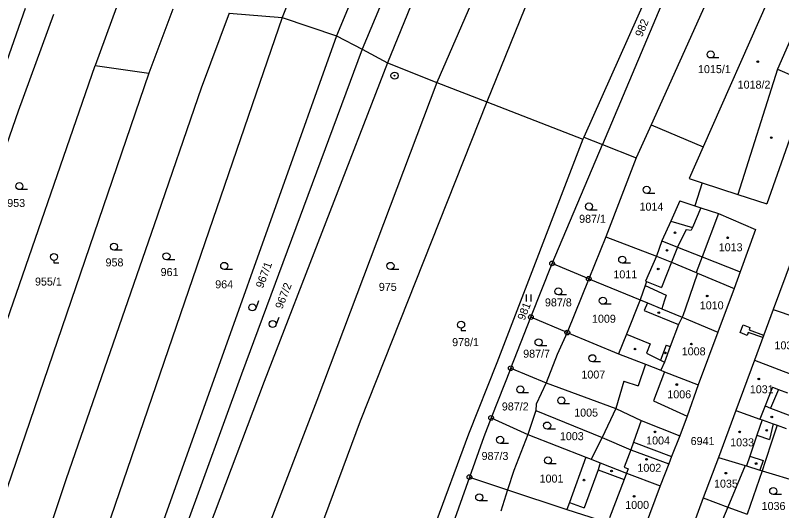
# Model space of a CAD drawing. Extents: x -593183 to -588034, y -1130415 to -1124994.
# Drawn here: x -591341.4 to -591178.8, y -1129005.4 to -1128900.2 of the extents above; entities that cross this region are included whole.
import ezdxf

# ---------------------------------------------------------------- set-up
doc = ezdxf.new("R2010")
doc.units = 0
for name, color, linetype in [('Vrstva 1', 7, 'Continuous'), ('Vrstva 18', 7, 'Continuous'), ('Vrstva 19', 7, 'Continuous'), ('Vrstva 24', 7, 'Continuous'), ('Vrstva 25', 7, 'Continuous'), ('Vrstva 27', 7, 'Continuous'), ('Vrstva 4', 7, 'Continuous')]:
    doc.layers.add(name, color=color, linetype=linetype)

msp = doc.modelspace()

# ---------------------------------------------------------------- linework, layer by layer
at = {"layer": 'Vrstva 1'}
for p, q in [((-591253.18, -1128872.07), (-591267.84, -1128907.4)), ((-591274.92, -1128875.91), (-591284.82, -1128900.6)), ((-591247.97, -1128874.78), (-591262.45, -1128910.29)), ((-591184.96, -1128875.53), (-591206.44, -1128923.42)), ((-591195.75, -1128877.7), (-591216.83, -1128927.62)), ((-591263.41, -1128880.52), (-591273.24, -1128904.52)), ((-591200.68, -1128880.96), (-591220.77, -1128926.07)), ((-591240.16, -1128887.18), (-591251.97, -1128914.47)), ((-591228.37, -1128886.57), (-591241.39, -1128918.58)), ((-591339.33, -1128898.75), (-591375.16, -1128999.99)), ((-591319.94, -1128898.41), (-591324.51, -1128910.84)), ((-591181.77, -1128897.25), (-591195.46, -1128928.12)), ((-591333.32, -1128900.02), (-591340.85, -1128920.55)), ((-591308.02, -1128898.88), (-591313.09, -1128912.48)), ((-591296.04, -1128899.72), (-591301.97, -1128915.65)), ((-591284.82, -1128900.6), (-591291.2, -1128919.2)), ((-591284.82, -1128900.6), (-591273.24, -1128904.52)), ((-591273.24, -1128904.52), (-591298.3, -1128974.83)), ((-591273.24, -1128904.52), (-591267.84, -1128907.4)), ((-591267.84, -1128907.4), (-591293.42, -1128976.43)), ((-591267.84, -1128907.4), (-591262.45, -1128910.29)), ((-591355.26, -1128999.87), (-591324.51, -1128910.84)), ((-591262.45, -1128910.29), (-591288.59, -1128978.01)), ((-591313.09, -1128912.48), (-591344.14, -1129003.51)), ((-591251.97, -1128914.47), (-591277.46, -1128982.03)), ((-591172.91, -1128914.55), (-591181.94, -1128940.23)), ((-591301.97, -1128915.65), (-591311.94, -1128944.66)), ((-591291.2, -1128919.2), (-591301.21, -1128948.55)), ((-591241.39, -1128918.58), (-591268.23, -1128986.43)), ((-591340.85, -1128920.55), (-591369.1, -1129001.43)), ((-591206.44, -1128923.42), (-591209.64, -1128930.47)), ((-591206.44, -1128923.42), (-591195.46, -1128928.12)), ((-591220.77, -1128926.07), (-591220.95, -1128926.48)), ((-591220.77, -1128926.07), (-591216.83, -1128927.62)), ((-591220.95, -1128926.48), (-591239.26, -1128974.04)), ((-591227.51, -1128952.91), (-591216.83, -1128927.62)), ((-591216.83, -1128927.62), (-591209.64, -1128930.47)), ((-591195.46, -1128928.12), (-591198.43, -1128934.82)), ((-591209.64, -1128930.47), (-591216.07, -1128947.22)), ((-591198.43, -1128934.82), (-591195.67, -1128935.75)), ((-591195.67, -1128935.75), (-591197.19, -1128940.68)), ((-591195.67, -1128935.75), (-591188.07, -1128938.22)), ((-591188.07, -1128938.22), (-591181.94, -1128940.23)), ((-591200.37, -1128939.61), (-591202.32, -1128943.95)), ((-591200.37, -1128939.61), (-591197.19, -1128940.68)), ((-591197.19, -1128940.68), (-591195.93, -1128941.07)), ((-591195.93, -1128941.07), (-591192.15, -1128942.26)), ((-591192.15, -1128942.26), (-591184.3, -1128945.67)), ((-591202.32, -1128943.95), (-591204.18, -1128948.09)), ((-591311.94, -1128944.66), (-591330.63, -1128998.65)), ((-591184.3, -1128945.67), (-591187.56, -1128954.71)), ((-591216.07, -1128947.22), (-591219.73, -1128956.16)), ((-591216.07, -1128947.22), (-591205.37, -1128951.32)), ((-591301.21, -1128948.55), (-591334.86, -1129046.79)), ((-591204.18, -1128948.09), (-591205.37, -1128951.32)), ((-591205.37, -1128951.32), (-591207.68, -1128956.69)), ((-591205.37, -1128951.32), (-591202.16, -1128952.64)), ((-591176.52, -1128951.85), (-591180.58, -1128962.67)), ((-591232, -1128964.3), (-591227.51, -1128952.91)), ((-591219.73, -1128956.16), (-591227.51, -1128952.91)), ((-591202.16, -1128952.64), (-591196.89, -1128954.81)), ((-591196.89, -1128954.81), (-591196.64, -1128954.95)), ((-591196.64, -1128954.95), (-591188.82, -1128958.23)), ((-591187.56, -1128954.71), (-591188.82, -1128958.23)), ((-591219.73, -1128956.16), (-591224.27, -1128967.58)), ((-591219.73, -1128956.16), (-591208.84, -1128960.65)), ((-591207.47, -1128956.77), (-591207.76, -1128957.61)), ((-591207.68, -1128956.69), (-591207.47, -1128956.77)), ((-591207.76, -1128957.61), (-591208.84, -1128960.65)), ((-591188.82, -1128958.23), (-591192.3, -1128967.48)), ((-591208.84, -1128960.65), (-591211.74, -1128967.96)), ((-591208.84, -1128960.65), (-591207.28, -1128961.3)), ((-591207.28, -1128961.3), (-591204.23, -1128962.53)), ((-591204.23, -1128962.53), (-591199.88, -1128964.31)), ((-591180.58, -1128962.67), (-591184.55, -1128973.43)), ((-591180.58, -1128962.67), (-591175.73, -1128964.35)), ((-591236.29, -1128975.17), (-591232, -1128964.3)), ((-591224.27, -1128967.58), (-591232, -1128964.3)), ((-591199.88, -1128964.31), (-591192.3, -1128967.48)), ((-591224.27, -1128967.58), (-591226.42, -1128972.22)), ((-591224.27, -1128967.58), (-591213.4, -1128972.12)), ((-591211.74, -1128967.96), (-591213.4, -1128972.12)), ((-591192.3, -1128967.48), (-591196.48, -1128978.68)), ((-591226.42, -1128972.22), (-591228.79, -1128978.29)), ((-591213.4, -1128972.12), (-591207.67, -1128974.33)), ((-591184.55, -1128973.43), (-591188.48, -1128984.14)), ((-591184.55, -1128973.43), (-591176.03, -1128976.71)), ((-591298.3, -1128974.83), (-591327.17, -1129055.6)), ((-591239.26, -1128974.04), (-591245.26, -1128989.18)), ((-591236.29, -1128975.17), (-591240.44, -1128985.71)), ((-591236.29, -1128975.17), (-591228.79, -1128978.29)), ((-591207.67, -1128974.33), (-591209.24, -1128978.92)), ((-591207.67, -1128974.33), (-591204.4, -1128975.59)), ((-591293.42, -1128976.43), (-591322.65, -1129056.55)), ((-591204.4, -1128975.59), (-591203.61, -1128975.94)), ((-591203.61, -1128975.94), (-591196.48, -1128978.68)), ((-591288.59, -1128978.01), (-591317.17, -1129053.44)), ((-591228.79, -1128978.29), (-591230.87, -1128982.83)), ((-591228.79, -1128978.29), (-591213.98, -1128983.73)), ((-591212.29, -1128977.95), (-591213.98, -1128983.73)), ((-591212.29, -1128977.95), (-591209.24, -1128978.92)), ((-591196.48, -1128978.68), (-591198.85, -1128985.35)), ((-591277.46, -1128982.03), (-591307.81, -1129061.25)), ((-591230.87, -1128982.83), (-591230.99, -1128984.17)), ((-591230.99, -1128984.17), (-591232.62, -1128989.23)), ((-591230.99, -1128984.17), (-591216.89, -1128989.86)), ((-591213.98, -1128983.73), (-591216.89, -1128989.86)), ((-591213.98, -1128983.73), (-591208.57, -1128986.31)), ((-591188.48, -1128984.14), (-591192.18, -1128994.11)), ((-591188.48, -1128984.14), (-591183.39, -1128985.97)), ((-591268.23, -1128986.43), (-591298.24, -1129066.98)), ((-591240.44, -1128985.71), (-591242.02, -1128989.72)), ((-591240.44, -1128985.71), (-591232.62, -1128989.23)), ((-591208.57, -1128986.31), (-591200.42, -1128989.51)), ((-591198.85, -1128985.35), (-591200.42, -1128989.51)), ((-591183.39, -1128985.97), (-591182.92, -1128986.14)), ((-591182.92, -1128986.14), (-591180.57, -1128986.99)), ((-591179.75, -1128987.29), (-591180.79, -1128990.47)), ((-591180.57, -1128986.99), (-591179.75, -1128987.29)), ((-591179.75, -1128987.29), (-591177.84, -1128987.98)), ((-591245.26, -1128989.18), (-591262.07, -1129034.56)), ((-591242.02, -1128989.72), (-591245.06, -1128998.31)), ((-591232.62, -1128989.23), (-591235.61, -1128996.93)), ((-591232.62, -1128989.23), (-591220.36, -1128994.07)), ((-591216.89, -1128989.86), (-591219.21, -1128994.52)), ((-591216.89, -1128989.86), (-591210.78, -1128992.5)), ((-591200.42, -1128989.51), (-591202.14, -1128993.93)), ((-591180.79, -1128990.47), (-591182.26, -1128994.96)), ((-591210.78, -1128992.5), (-591202.75, -1128995.52)), ((-591220.36, -1128994.07), (-591223.82, -1129003.72)), ((-591220.36, -1128994.07), (-591219.21, -1128994.52)), ((-591219.21, -1128994.52), (-591217.27, -1128995.28)), ((-591202.14, -1128993.93), (-591202.75, -1128995.52)), ((-591192.18, -1128994.11), (-591195.42, -1129002.71)), ((-591192.18, -1128994.11), (-591186.53, -1128995.85)), ((-591217.27, -1128995.28), (-591211.71, -1128997.45)), ((-591202.75, -1128995.52), (-591204.58, -1129000.17)), ((-591186.53, -1128995.85), (-591186.22, -1128995.94)), ((-591186.22, -1128995.94), (-591183.38, -1128996.82)), ((-591182.26, -1128994.96), (-591182.91, -1128996.96)), ((-591235.61, -1128996.93), (-591236.94, -1129001.02)), ((-591211.71, -1128997.45), (-591204.58, -1129000.17)), ((-591182.91, -1128996.96), (-591186.06, -1129006.21)), ((-591183.38, -1128996.82), (-591182.91, -1128996.96)), ((-591182.91, -1128996.96), (-591174.67, -1128999.49)), ((-591330.63, -1128998.65), (-591343.79, -1129037.78)), ((-591245.06, -1128998.31), (-591249.19, -1129010.01)), ((-591245.06, -1128998.31), (-591236.94, -1129001.02)), ((-591236.94, -1129001.02), (-591238.41, -1129005.57)), ((-591236.94, -1129001.02), (-591224.34, -1129005.16)), ((-591204.58, -1129000.17), (-591208.07, -1129009.58)), ((-591195.42, -1129002.71), (-591199.39, -1129013.48)), ((-591195.42, -1129002.71), (-591190.18, -1129004.67)), ((-591223.82, -1129003.72), (-591224.34, -1129005.16)), ((-591224.34, -1129005.16), (-591217.72, -1129007.34)), ((-591190.18, -1129004.67), (-591186.06, -1129006.21))]:
    msp.add_line(p, q, dxfattribs=at)
at = {"layer": 'Vrstva 24'}
for centre, radius in [((-591260.95, -1128912.99), 0.75), ((-591260.95, -1128912.99), 0.0903), ((-591227.51, -1128952.91), 0.5), ((-591227.51, -1128952.91), 0.0327), ((-591219.73, -1128956.16), 0.5), ((-591219.73, -1128956.16), 0.0327), ((-591232, -1128964.3), 0.5), ((-591232, -1128964.3), 0.0327), ((-591224.27, -1128967.58), 0.5), ((-591224.27, -1128967.58), 0.0327), ((-591236.29, -1128975.17), 0.5), ((-591236.29, -1128975.17), 0.0327), ((-591240.44, -1128985.71), 0.5), ((-591240.44, -1128985.71), 0.0327), ((-591245.06, -1128998.31), 0.5), ((-591245.06, -1128998.31), 0.0327)]:
    msp.add_circle(centre, radius, dxfattribs=at)
at = {"layer": 'Vrstva 25'}
for p, q in [((-591192.09, -1128909.24), (-591193.84, -1128909.24)), ((-591338.83, -1128937.22), (-591340.58, -1128937.22)), ((-591205.67, -1128938.01), (-591207.42, -1128938.01)), ((-591217.92, -1128941.55), (-591219.67, -1128941.55)), ((-591318.76, -1128950.08), (-591320.51, -1128950.08)), ((-591333.25, -1128952.27), (-591333.25, -1128952.77)), ((-591307.61, -1128952.13), (-591309.36, -1128952.13)), ((-591333.25, -1128952.77), (-591332.23, -1128952.77)), ((-591210.86, -1128952.86), (-591212.61, -1128952.86)), ((-591295.35, -1128954.17), (-591297.1, -1128954.17)), ((-591260.06, -1128954.17), (-591261.81, -1128954.17)), ((-591232.98, -1128959.5), (-591232.98, -1128961)), ((-591231.96, -1128961), (-591231.96, -1128959.5)), ((-591224.44, -1128959.59), (-591226.19, -1128959.59)), ((-591289.86, -1128960.82), (-591290.41, -1128962.48)), ((-591214.98, -1128961.58), (-591216.73, -1128961.58)), ((-591285.49, -1128964.41), (-591286.13, -1128966.04)), ((-591246.82, -1128966.67), (-591246.82, -1128967.17)), ((-591246.82, -1128967.17), (-591245.8, -1128967.17)), ((-591228.63, -1128970.42), (-591230.38, -1128970.42)), ((-591217.2, -1128973.79), (-591218.95, -1128973.79)), ((-591232.5, -1128980.43), (-591234.25, -1128980.43)), ((-591223.8, -1128982.76), (-591225.55, -1128982.76)), ((-591226.8, -1128988.1), (-591228.55, -1128988.1)), ((-591236.79, -1128991.14), (-591238.54, -1128991.14)), ((-591226.63, -1128995.5), (-591228.38, -1128995.5)), ((-591178.81, -1129002.02), (-591180.56, -1129002.02)), ((-591241.22, -1129003.36), (-591242.97, -1129003.36))]:
    msp.add_line(p, q, dxfattribs=at)
for centre, radius in [((-591193.84, -1128908.49), 0.75), ((-591183.84, -1128910.03), 0.175), ((-591183.84, -1128910.03), 0.15), ((-591180.97, -1128926.16), 0.175), ((-591340.58, -1128936.47), 0.75), ((-591207.42, -1128937.26), 0.75), ((-591219.67, -1128940.8), 0.75), ((-591201.4, -1128946.38), 0.175), ((-591190.25, -1128947.45), 0.175), ((-591190.25, -1128947.45), 0.15), ((-591320.51, -1128949.33), 0.75), ((-591333.25, -1128951.52), 0.75), ((-591309.36, -1128951.38), 0.75), ((-591203.11, -1128950.13), 0.175), ((-591212.61, -1128952.11), 0.75), ((-591297.1, -1128953.42), 0.75), ((-591261.81, -1128953.42), 0.75), ((-591204.97, -1128954.08), 0.175), ((-591226.19, -1128958.84), 0.75), ((-591216.73, -1128960.83), 0.75), ((-591194.57, -1128959.81), 0.175), ((-591194.57, -1128959.81), 0.15), ((-591291.12, -1128962.24), 0.75), ((-591204.85, -1128963.36), 0.175), ((-591286.83, -1128965.77), 0.75), ((-591246.82, -1128965.92), 0.75), ((-591230.38, -1128969.67), 0.75), ((-591197.93, -1128970.03), 0.175), ((-591197.93, -1128970.03), 0.15), ((-591209.89, -1128971.09), 0.175), ((-591203.48, -1128971.9), 0.175), ((-591218.95, -1128973.04), 0.75), ((-591201.04, -1128978.63), 0.175), ((-591201.04, -1128978.63), 0.15), ((-591183.62, -1128977.45), 0.175), ((-591183.62, -1128977.45), 0.15), ((-591234.25, -1128979.68), 0.75), ((-591225.55, -1128982.01), 0.75), ((-591228.55, -1128987.35), 0.75), ((-591180.87, -1128985.52), 0.175), ((-591181.94, -1128988.36), 0.175), ((-591238.54, -1128990.39), 0.75), ((-591205.65, -1128988.69), 0.175), ((-591205.65, -1128988.69), 0.15), ((-591187.68, -1128988.69), 0.175), ((-591187.68, -1128988.69), 0.15), ((-591228.38, -1128994.75), 0.75), ((-591207.45, -1128994.52), 0.175), ((-591207.45, -1128994.52), 0.15), ((-591184.19, -1128995.43), 0.175), ((-591214.89, -1128997.01), 0.175), ((-591190.61, -1128997.47), 0.175), ((-591190.61, -1128997.47), 0.15), ((-591220.73, -1128998.94), 0.175), ((-591180.56, -1129001.27), 0.75), ((-591242.97, -1129002.61), 0.75), ((-591210.09, -1129002.4), 0.175), ((-591210.09, -1129002.4), 0.15)]:
    msp.add_circle(centre, radius, dxfattribs=at)
at = {"layer": 'Vrstva 27'}
for p, q in [((-591187.56, -1128967.58), (-591186.97, -1128965.98)), ((-591186.97, -1128965.98), (-591185.5, -1128966.54)), ((-591185.5, -1128966.54), (-591185.66, -1128967)), ((-591185.66, -1128967), (-591182.6, -1128968.14)), ((-591186.07, -1128968.18), (-591187.56, -1128967.58)), ((-591185.88, -1128967.58), (-591186.07, -1128968.18)), ((-591182.79, -1128968.67), (-591185.88, -1128967.58)), ((-591182.6, -1128968.14), (-591182.79, -1128968.67))]:
    msp.add_line(p, q, dxfattribs=at)
at = {"layer": 'Vrstva 4'}
for p, q in [((-591296.04, -1128899.72), (-591284.82, -1128900.6)), ((-591174.74, -1128900.32), (-591179.64, -1128911.6)), ((-591324.51, -1128910.84), (-591313.09, -1128912.48)), ((-591262.45, -1128910.29), (-591251.97, -1128914.47)), ((-591179.64, -1128911.6), (-591188.07, -1128938.22)), ((-591179.64, -1128911.6), (-591176.05, -1128913.15)), ((-591251.97, -1128914.47), (-591241.39, -1128918.58)), ((-591241.39, -1128918.58), (-591220.95, -1128926.48)), ((-591195.93, -1128941.07), (-591197.71, -1128945.29)), ((-591192.15, -1128942.26), (-591195.67, -1128951.5)), ((-591202.32, -1128943.95), (-591197.71, -1128945.29)), ((-591199.02, -1128945.7), (-591200.89, -1128949.44)), ((-591199.02, -1128945.7), (-591197.95, -1128945.86)), ((-591197.71, -1128945.29), (-591197.95, -1128945.86)), ((-591204.18, -1128948.09), (-591200.89, -1128949.44)), ((-591200.89, -1128949.44), (-591202.16, -1128952.64)), ((-591200.89, -1128949.44), (-591195.67, -1128951.5)), ((-591195.67, -1128951.5), (-591196.89, -1128954.81)), ((-591195.67, -1128951.5), (-591187.56, -1128954.71)), ((-591202.16, -1128952.64), (-591204.31, -1128958.03)), ((-591196.64, -1128954.95), (-591199.21, -1128962.38)), ((-591207.47, -1128956.77), (-591204.31, -1128958.03)), ((-591207.76, -1128957.61), (-591203.3, -1128959.61)), ((-591203.3, -1128959.61), (-591203.67, -1128960.73)), ((-591207.28, -1128961.3), (-591207.93, -1128962.88)), ((-591204.02, -1128961.86), (-591204.23, -1128962.53)), ((-591203.67, -1128960.73), (-591204.02, -1128961.86)), ((-591207.93, -1128962.88), (-591200.67, -1128965.88)), ((-591199.21, -1128962.38), (-591199.78, -1128964.02)), ((-591199.88, -1128964.31), (-591200.67, -1128965.88)), ((-591199.78, -1128964.02), (-591199.88, -1128964.31)), ((-591200.67, -1128965.88), (-591202.46, -1128970.55)), ((-591211.74, -1128967.96), (-591206.7, -1128969.96)), ((-591206.7, -1128969.96), (-591207.49, -1128971.95)), ((-591203.26, -1128970.24), (-591204.51, -1128973.44)), ((-591203.26, -1128970.24), (-591202.46, -1128970.55)), ((-591207.49, -1128971.95), (-591204.51, -1128973.44)), ((-591202.46, -1128970.55), (-591203.62, -1128973.88)), ((-591204.51, -1128973.44), (-591203.62, -1128973.88)), ((-591203.62, -1128973.88), (-591204.4, -1128975.59)), ((-591203.61, -1128975.94), (-591205.96, -1128982.07)), ((-591180.74, -1128979.17), (-591182.3, -1128983.17)), ((-591179.43, -1128979.67), (-591181.13, -1128983.63)), ((-591180.74, -1128979.17), (-591179.43, -1128979.67)), ((-591179.43, -1128979.67), (-591177.52, -1128980.42)), ((-591205.96, -1128982.07), (-591198.85, -1128985.35)), ((-591182.3, -1128983.17), (-591183.39, -1128985.97)), ((-591182.3, -1128983.17), (-591181.13, -1128983.63)), ((-591181.13, -1128983.63), (-591176.8, -1128985.31)), ((-591208.57, -1128986.31), (-591210.21, -1128990.9)), ((-591182.92, -1128986.14), (-591184.02, -1128989.4)), ((-591180.57, -1128986.99), (-591181.32, -1128990.31)), ((-591184.02, -1128989.4), (-591185.53, -1128993.89)), ((-591184.02, -1128989.4), (-591181.32, -1128990.31)), ((-591210.21, -1128990.9), (-591210.78, -1128992.5)), ((-591210.21, -1128990.9), (-591202.14, -1128993.93)), ((-591210.78, -1128992.5), (-591212.21, -1128996.22)), ((-591185.53, -1128993.89), (-591186.22, -1128995.94)), ((-591185.53, -1128993.89), (-591182.72, -1128994.81)), ((-591217.27, -1128995.28), (-591217.73, -1128996.77)), ((-591212.21, -1128996.22), (-591211.37, -1128996.52)), ((-591186.53, -1128995.85), (-591190.18, -1129004.67)), ((-591182.72, -1128994.81), (-591183.38, -1128996.82)), ((-591217.73, -1128996.77), (-591220.7, -1129004.84)), ((-591217.73, -1128996.77), (-591212.2, -1128998.8)), ((-591211.71, -1128997.45), (-591212.2, -1128998.8)), ((-591211.37, -1128996.52), (-591211.71, -1128997.45)), ((-591212.2, -1128998.8), (-591215.33, -1129006.95)), ((-591223.82, -1129003.72), (-591220.7, -1129004.84)), ((-591190.18, -1129004.67), (-591191.3, -1129007.38))]:
    msp.add_line(p, q, dxfattribs=at)

# ---------------------------------------------------------------- texts
at = {"layer": 'Vrstva 18'}
for s, rotation, p in [('982', 67.3996, (-591208.41, -1128904.91)), ('967/1', 69.6671, (-591288.88, -1128958.29)), ('967/2', 68.8934, (-591284.78, -1128962.72)), ('981', 68.499, (-591233.37, -1128965.13))]:
    msp.add_text(s, height=1.7, rotation=rotation, dxfattribs=at).set_placement(p)
for s, p in [('1015/1', (-591196.53, -1128912.46)), ('953', (-591343.16, -1128940.9)), ('1014', (-591208.94, -1128941.68)), ('987/1', (-591221.76, -1128944.26)), ('958', (-591322.29, -1128953.53)), ('961', (-591310.6, -1128955.58)), ('1011', (-591214.49, -1128956.07)), ('955/1', (-591337.27, -1128957.6)), ('964', (-591299.01, -1128958.18)), ('975', (-591264.28, -1128958.73)), ('987/8', (-591229.02, -1128962.03)), ('1009', (-591219.03, -1128965.5)), ('978/1', (-591248.72, -1128970.47)), ('987/7', (-591233.64, -1128972.93)), ('1007', (-591221.28, -1128977.36)), ('987/2', (-591238.17, -1128984.14)), ('1005', (-591222.81, -1128985.45)), ('1003', (-591225.85, -1128990.46)), ('6941', (-591198.09, -1128991.49)), ('987/3', (-591242.47, -1128994.66)), ('1001', (-591230.15, -1128999.47)), ('1036', (-591183.02, -1129005.29))]:
    msp.add_text(s, height=1.7, dxfattribs=at).set_placement(p)
at = {"layer": 'Vrstva 19'}
for s, p in [('1018/2', (-591188.11, -1128915.75)), ('1013', (-591192.13, -1128950.31)), ('1010', (-591196.15, -1128962.65)), ('1030', (-591180.3, -1128971.16)), ('1008', (-591199.98, -1128972.43)), ('1006', (-591203.04, -1128981.56)), ('1031', (-591185.53, -1128980.49)), ('1004', (-591207.54, -1128991.37)), ('1033', (-591189.7, -1128991.77)), ('1002', (-591209.39, -1128997.18)), ('1035', (-591193.13, -1129000.54)), ('1000', (-591211.98, -1129005.06))]:
    msp.add_text(s, height=1.7, dxfattribs=at).set_placement(p)

doc.saveas('drawing.dxf')
